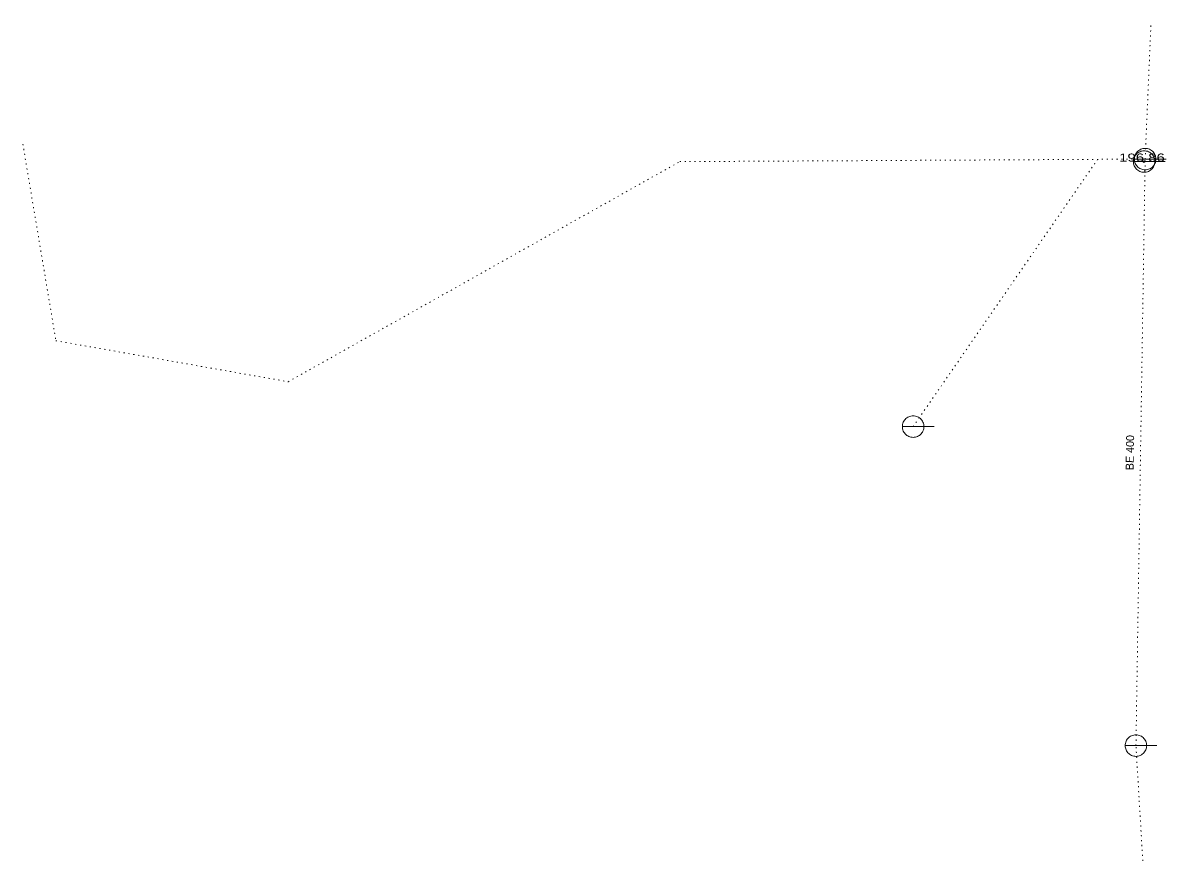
# Model space of a CAD drawing. Extents: x -688177 to -687620, y -1056713 to -1056287.
# Drawn here: x -688176.8 to -688069.7, y -1056581.7 to -1056503.8 of the extents above; entities that cross this region are included whole.
import ezdxf
from ezdxf.enums import TextEntityAlignment as Align

# ---------------------------------------------------------------- set-up
doc = ezdxf.new("R2010")
doc.units = 0
doc.header["$LTSCALE"] = 0.3
doc.header["$PDMODE"] = 32
doc.header["$PDSIZE"] = 0.15
doc.linetypes.add('DOTTED', pattern=[1.5, 0.3, -1.2])
for name, color, linetype in [('1', 7, 'Continuous'), ('18', 7, 'Continuous'), ('3', 7, 'Continuous')]:
    doc.layers.add(name, color=color, linetype=linetype)
for name, color, linetype, lineweight in [('12', 7, 'Continuous', 13), ('31', 7, 'DOTTED', 13), ('41', 7, 'DOTTED', 13), ('46', 7, 'DOTTED', 13)]:
    doc.layers.add(name, color=color, linetype=linetype, lineweight=lineweight)

msp = doc.modelspace()

# ---------------------------------------------------------------- linework, layer by layer
at = {"layer": '1'}
msp.add_point((-688071.73, -1056516.81), dxfattribs=at)
at = {"layer": '12'}
for p, q in [((-688072.638, -1056516.58), (-688069.662, -1056516.58)), ((-688072.738, -1056516.81), (-688069.762, -1056516.81)), ((-688094.378, -1056541.66), (-688091.402, -1056541.66)), ((-688073.498, -1056571.56), (-688070.522, -1056571.56))]:
    msp.add_line(p, q, dxfattribs=at)
for points in [[(-688071.63, -1056515.572), (-688071.735, -1056515.578), (-688071.839, -1056515.594), (-688071.941, -1056515.622), (-688072.04, -1056515.66), (-688072.134, -1056515.707), (-688072.222, -1056515.765), (-688072.304, -1056515.831), (-688072.379, -1056515.906), (-688072.445, -1056515.988), (-688072.503, -1056516.076), (-688072.55, -1056516.17), (-688072.588, -1056516.269), (-688072.616, -1056516.371), (-688072.632, -1056516.475), (-688072.638, -1056516.58), (-688072.632, -1056516.685), (-688072.616, -1056516.79), (-688072.588, -1056516.892), (-688072.55, -1056516.99), (-688072.503, -1056517.084), (-688072.445, -1056517.173), (-688072.379, -1056517.255), (-688072.304, -1056517.329), (-688072.222, -1056517.395), (-688072.134, -1056517.453), (-688072.04, -1056517.501), (-688071.941, -1056517.539), (-688071.839, -1056517.566), (-688071.735, -1056517.582), (-688071.63, -1056517.588), (-688071.525, -1056517.582), (-688071.42, -1056517.566), (-688071.318, -1056517.539), (-688071.22, -1056517.501), (-688071.126, -1056517.453), (-688071.037, -1056517.395), (-688070.955, -1056517.329), (-688070.881, -1056517.255), (-688070.815, -1056517.173), (-688070.757, -1056517.084), (-688070.709, -1056516.99), (-688070.671, -1056516.892), (-688070.644, -1056516.79), (-688070.628, -1056516.685), (-688070.622, -1056516.58), (-688070.628, -1056516.475), (-688070.644, -1056516.371), (-688070.671, -1056516.269), (-688070.709, -1056516.17), (-688070.757, -1056516.076), (-688070.815, -1056515.988), (-688070.881, -1056515.906), (-688070.955, -1056515.831), (-688071.037, -1056515.765), (-688071.126, -1056515.707), (-688071.22, -1056515.66), (-688071.318, -1056515.622), (-688071.42, -1056515.594), (-688071.525, -1056515.578)], [(-688071.73, -1056515.802), (-688071.835, -1056515.808), (-688071.939, -1056515.824), (-688072.041, -1056515.852), (-688072.14, -1056515.89), (-688072.234, -1056515.937), (-688072.322, -1056515.995), (-688072.404, -1056516.061), (-688072.479, -1056516.136), (-688072.545, -1056516.218), (-688072.603, -1056516.306), (-688072.65, -1056516.4), (-688072.688, -1056516.499), (-688072.716, -1056516.601), (-688072.732, -1056516.705), (-688072.738, -1056516.81), (-688072.732, -1056516.915), (-688072.716, -1056517.02), (-688072.688, -1056517.122), (-688072.65, -1056517.22), (-688072.603, -1056517.314), (-688072.545, -1056517.403), (-688072.479, -1056517.485), (-688072.404, -1056517.559), (-688072.322, -1056517.625), (-688072.234, -1056517.683), (-688072.14, -1056517.731), (-688072.041, -1056517.769), (-688071.939, -1056517.796), (-688071.835, -1056517.812), (-688071.73, -1056517.818), (-688071.625, -1056517.812), (-688071.52, -1056517.796), (-688071.418, -1056517.769), (-688071.32, -1056517.731), (-688071.226, -1056517.683), (-688071.137, -1056517.625), (-688071.055, -1056517.559), (-688070.981, -1056517.485), (-688070.915, -1056517.403), (-688070.857, -1056517.314), (-688070.809, -1056517.22), (-688070.771, -1056517.122), (-688070.744, -1056517.02), (-688070.728, -1056516.915), (-688070.722, -1056516.81), (-688070.728, -1056516.705), (-688070.744, -1056516.601), (-688070.771, -1056516.499), (-688070.809, -1056516.4), (-688070.857, -1056516.306), (-688070.915, -1056516.218), (-688070.981, -1056516.136), (-688071.055, -1056516.061), (-688071.137, -1056515.995), (-688071.226, -1056515.937), (-688071.32, -1056515.89), (-688071.418, -1056515.852), (-688071.52, -1056515.824), (-688071.625, -1056515.808)], [(-688093.37, -1056540.652), (-688093.475, -1056540.658), (-688093.579, -1056540.674), (-688093.681, -1056540.702), (-688093.78, -1056540.74), (-688093.874, -1056540.787), (-688093.962, -1056540.845), (-688094.044, -1056540.911), (-688094.119, -1056540.986), (-688094.185, -1056541.068), (-688094.243, -1056541.156), (-688094.29, -1056541.25), (-688094.328, -1056541.349), (-688094.356, -1056541.451), (-688094.372, -1056541.555), (-688094.378, -1056541.66), (-688094.372, -1056541.765), (-688094.356, -1056541.87), (-688094.328, -1056541.972), (-688094.29, -1056542.07), (-688094.243, -1056542.164), (-688094.185, -1056542.253), (-688094.119, -1056542.335), (-688094.044, -1056542.409), (-688093.962, -1056542.475), (-688093.874, -1056542.533), (-688093.78, -1056542.581), (-688093.681, -1056542.619), (-688093.579, -1056542.646), (-688093.475, -1056542.662), (-688093.37, -1056542.668), (-688093.265, -1056542.662), (-688093.16, -1056542.646), (-688093.058, -1056542.619), (-688092.96, -1056542.581), (-688092.866, -1056542.533), (-688092.777, -1056542.475), (-688092.695, -1056542.409), (-688092.621, -1056542.335), (-688092.555, -1056542.253), (-688092.497, -1056542.164), (-688092.449, -1056542.07), (-688092.411, -1056541.972), (-688092.384, -1056541.87), (-688092.368, -1056541.765), (-688092.362, -1056541.66), (-688092.368, -1056541.555), (-688092.384, -1056541.451), (-688092.411, -1056541.349), (-688092.449, -1056541.25), (-688092.497, -1056541.156), (-688092.555, -1056541.068), (-688092.621, -1056540.986), (-688092.695, -1056540.911), (-688092.777, -1056540.845), (-688092.866, -1056540.787), (-688092.96, -1056540.74), (-688093.058, -1056540.702), (-688093.16, -1056540.674), (-688093.265, -1056540.658)], [(-688072.49, -1056570.552), (-688072.595, -1056570.558), (-688072.699, -1056570.574), (-688072.801, -1056570.602), (-688072.9, -1056570.64), (-688072.994, -1056570.687), (-688073.082, -1056570.745), (-688073.164, -1056570.811), (-688073.239, -1056570.886), (-688073.305, -1056570.968), (-688073.363, -1056571.056), (-688073.41, -1056571.15), (-688073.448, -1056571.249), (-688073.476, -1056571.351), (-688073.492, -1056571.455), (-688073.498, -1056571.56), (-688073.492, -1056571.665), (-688073.476, -1056571.77), (-688073.448, -1056571.872), (-688073.41, -1056571.97), (-688073.363, -1056572.064), (-688073.305, -1056572.153), (-688073.239, -1056572.235), (-688073.164, -1056572.309), (-688073.082, -1056572.375), (-688072.994, -1056572.433), (-688072.9, -1056572.481), (-688072.801, -1056572.519), (-688072.699, -1056572.546), (-688072.595, -1056572.562), (-688072.49, -1056572.568), (-688072.385, -1056572.562), (-688072.28, -1056572.546), (-688072.178, -1056572.519), (-688072.08, -1056572.481), (-688071.986, -1056572.433), (-688071.897, -1056572.375), (-688071.815, -1056572.309), (-688071.741, -1056572.235), (-688071.675, -1056572.153), (-688071.617, -1056572.064), (-688071.569, -1056571.97), (-688071.531, -1056571.872), (-688071.504, -1056571.77), (-688071.488, -1056571.665), (-688071.482, -1056571.56), (-688071.488, -1056571.455), (-688071.504, -1056571.351), (-688071.531, -1056571.249), (-688071.569, -1056571.15), (-688071.617, -1056571.056), (-688071.675, -1056570.968), (-688071.741, -1056570.886), (-688071.815, -1056570.811), (-688071.897, -1056570.745), (-688071.986, -1056570.687), (-688072.08, -1056570.64), (-688072.178, -1056570.602), (-688072.28, -1056570.574), (-688072.385, -1056570.558)]]:
    msp.add_lwpolyline(points, close=True, dxfattribs=at)
at = {"layer": '31'}
msp.add_line((-688093.37, -1056541.66), (-688076.1, -1056516.63), dxfattribs=at)
at = {"layer": '41'}
msp.add_lwpolyline([(-688176.8, -1056515.18), (-688173.7, -1056533.61), (-688151.93, -1056537.45), (-688115.24, -1056516.82), (-688071.63, -1056516.58)], dxfattribs=at)
at = {"layer": '46'}
for p, q in [((-688071.63, -1056516.58), (-688071.08, -1056503.81)), ((-688072.49, -1056571.56), (-688071.63, -1056516.58))]:
    msp.add_line(p, q, dxfattribs=at)
msp.add_lwpolyline([(-688106.71, -1056687), (-688094.37, -1056670.45), (-688071.74, -1056584.19), (-688072.49, -1056571.56)], dxfattribs=at)

# ---------------------------------------------------------------- texts
at = {"layer": '18'}
msp.add_text('BE 400', height=0.75, rotation=89.104, dxfattribs=at).set_placement((-688072.711, -1056545.744))
at = {"layer": '3', "width": 1.4}
msp.add_text('196 86 ', height=0.75, dxfattribs=at).set_placement((-688071.73, -1056516.81), align=Align.CENTER)

doc.saveas('drawing.dxf')
